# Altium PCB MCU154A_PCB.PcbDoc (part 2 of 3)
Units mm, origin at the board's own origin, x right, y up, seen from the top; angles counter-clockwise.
Board outline 105 x 85 mm, 2 copper layers (Top Layer, Bottom Layer), stack 1.6 mm thick; 186 components, 100 nets, 433 pads, 196 vias.
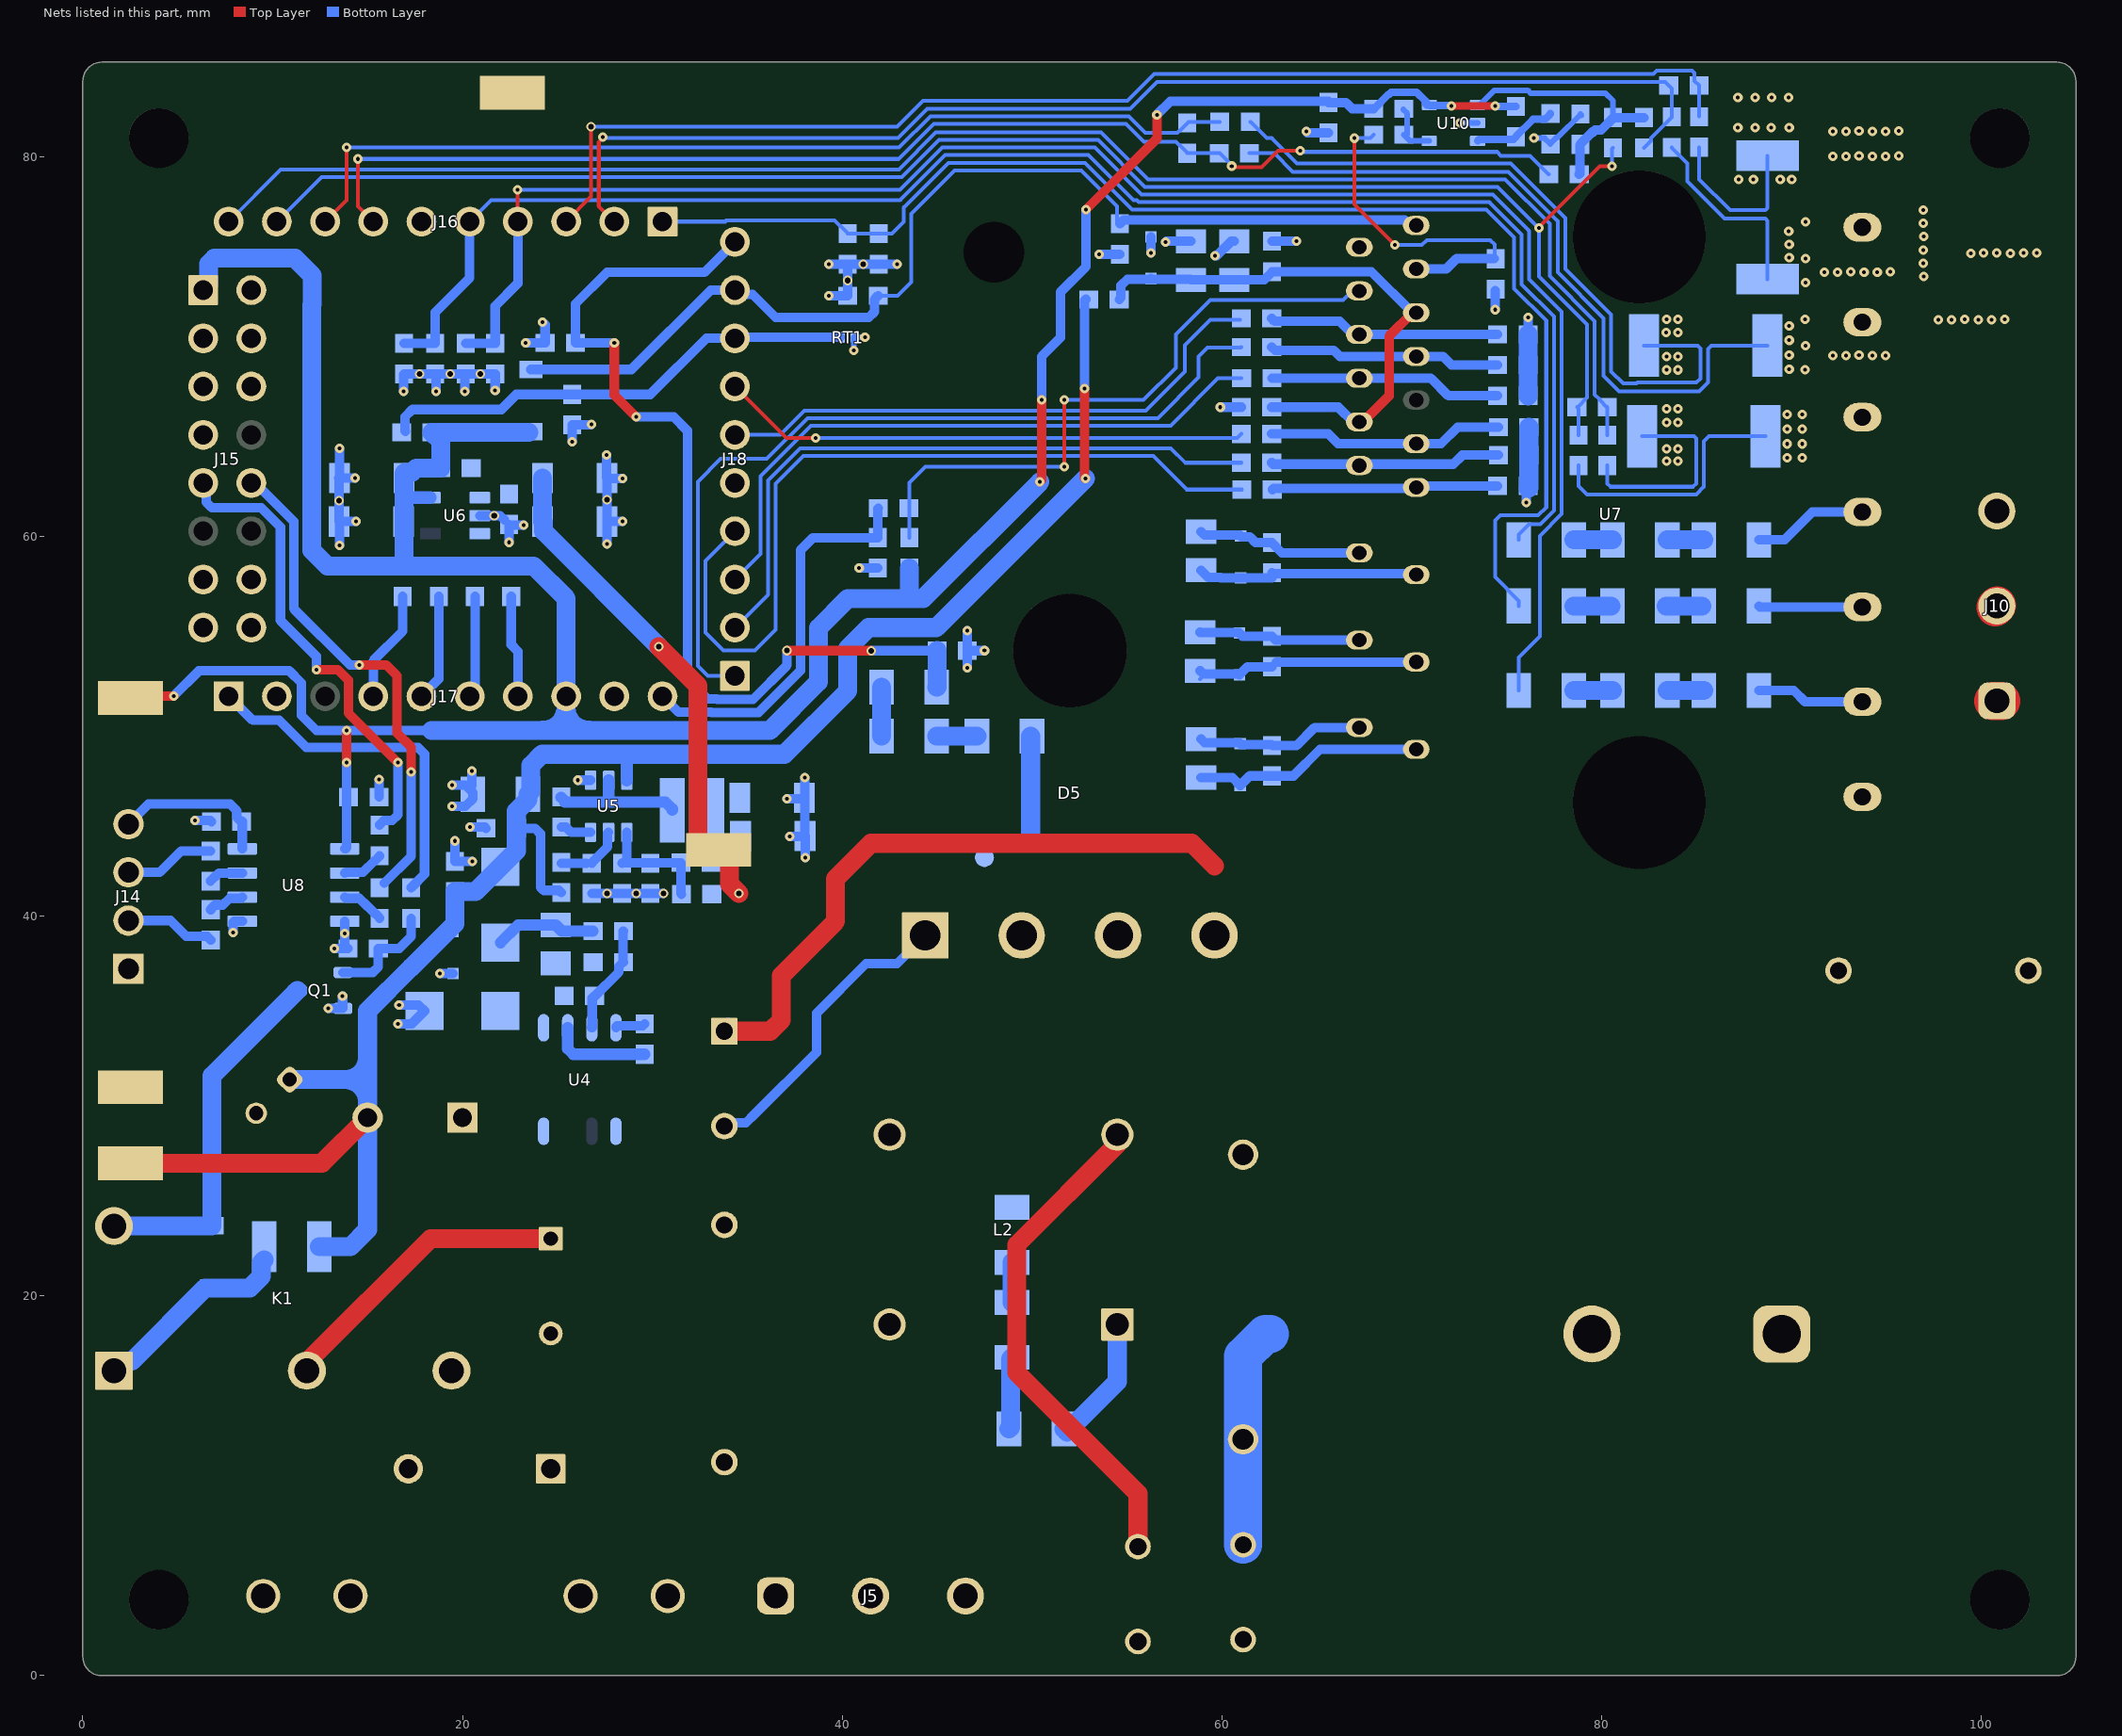
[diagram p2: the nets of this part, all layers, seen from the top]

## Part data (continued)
L3: library part CMP-0064862-2, "Inductor, Shielded Drum Core, Metal Composite, 1.8 mH, 0.35 A, 2.7 ohm, TH", Manufacturer="Wurth Elektronik", Supplier Part Number 1=732-3264-ND, Value1="2.7 ohm", Value2=0.35A, ValueDisplayed=1.8mH
L4: library part CMP-0064362-1, "Inductor, Shielded, Powdered Iron, 6.8 uH, 1.1 A, 0.287 ohm, AEC-Q200 Grade 1, SMD", Manufacturer="Wurth Elektronik", Supplier Part Number 1=732-6942-1-ND, Value1="0.287 ohm", Value2=1.1A, ValueDisplayed=6.8uH
LBL1: library part CMP-0003625-1, "Thermal Transfer Printable Labels, 0.650\" W x 0.200\" H - 10,000 per roll", Manufacturer=Brady, Supplier Part Number 1=97C5133
Logo1: library part CMP-0074844-1
Logo2: library part CMP-0074838-1, "Texas Instrument Corporate Signature"
Logo3: library part CMP-0074847-1, "FCC_disclaimer"
Logo4: library part CMP-0074769-1
LOGO5 LOGO7: library part CMP-0074837-1, "IEC 61010-1 Hot Surface Warning"
LOGO6 LOGO8: library part CMP-0074835-1, "IEC 61010-1 High Voltage Warning"
MP1 MP2 MP3 MP4: library part CMP-0087151-1, Manufacturer="Wurth Electronics"
Q1: library part CMP-0000775-2, "MOSFET, N-CH, 60 V, 0.36 A, SOT-23", Alternate Manufacturer=None, Manufacturer=Nexperia, Supplier Part Number 1=568-5818-1-ND, Value2="0.6 nC"
R8 R55 R85 R88 R97 R98: library part CMP-0022908-4, "RES, 20.0, 1%, 0.1 W, 0603", Manufacturer=Yageo, Power_W=100mW, Supplier Part Number 1=311-20.0HRCT-ND, TempCo="100 ppm/C", Tolerance_%=1%, Value2=0.1W, Value_Code=20R0, ValueDisplayed=20.0
R36 R77 R93 R94 R108: library part CMP-0022895-5, "RES, 1.00 k, 1%, 0.1 W, 0603", Manufacturer=Yageo, Power_W=100mW, Supplier Part Number 1=311-1.00KHRCT-ND, TempCo="100 ppm/C", Tolerance_%=1%, Value2=0.1W, Value_Code=1k00, ValueDisplayed=1.00k
R37: library part CMP-0082820-1, "RES, 180, 1%, 0.5 W, 1210", Manufacturer=Yageo, Power_W=500mW, TempCo="100 ppm/C", Tolerance_%=1%, Value2=0.5W, Value_Code=180R, ValueDisplayed=180
R38 R43 R78 R100 R101 R102 R103: library part CMP-0022746-5, "RES, 10.0 k, 1%, 0.1 W, 0603", Manufacturer=Yageo, Power_W=100mW, Supplier Part Number 1=311-10.0KHRCT-ND, TempCo="100 ppm/C", Tolerance_%=1%, Value2=0.1W, Value_Code=10k0, ValueDisplayed=10.0k
R39: library part CMP-0096764-1, "PTC Thermistor 70 Ohms Disc, 13mm Dia x 7.5mm W", Digikey Part Number=495-76143-ND, Manufacturer=TDK, Mouser Part Number=871-B59770C120A70, Operating Temperature Range="-40°C to +125°C", Tolerance_%=25%
R40 R52: library part CMP-0022786-4, "RES, 133 k, 1%, 0.1 W, 0603", Manufacturer=Yageo, Power_W=100mW, Supplier Part Number 1=311-133KHRCT-ND, TempCo="100 ppm/C", Tolerance_%=1%, Value2=0.1W, Value_Code=133k
R41 R44 R45: library part CMP-0017836-1, "RES, 100 k, 1%, 0.25 W, 1206", Manufacturer="Yageo America", Power_W=250mW, Supplier Part Number 1=311-100KFRCT-ND, TempCo="100 ppm/C", Tolerance_%=1%, Value2=0.25W, Value_Code=100k
R42: library part CMP-0097027-1, "3 kA Varistor 1 Circuit Through Hole Disc 13.2mm", Clamping Voltage=730V, Digikey Part Number=118-ISOM3-275-B-L2-ND, Manufacturer=Bourns, Mouser Part Number=652-ISOM3-275-B-L2, Operating Temperature Range="-40°C to +125°C", ValueDisplayed=30pF
R46 R56 R107 R109: library part CMP-0022906-5, "RES, 20.0 k, 1%, 0.1 W, 0603", Manufacturer=Yageo, Power_W=100mW, Supplier Part Number 1=311-20.0KHRCT-ND, TempCo="100 ppm/C", Tolerance_%=1%, Value2=0.1W, Value_Code=20k0, ValueDisplayed=20.0k
R47 R48 R54 R62 R63 R64 R67 R68 R69 R70 R71 R72: library part CMP-0018207-2, "RES, 332 k, 1%, 0.25 W, 1206", Manufacturer="Yageo America", Power_W=250mW, Supplier Part Number 1=311-332KFRCT-ND, TempCo="100 ppm/C", Tolerance_%=1%, Value2=0.25W, Value_Code=332k
R49: library part CMP-0022898-4, "RES, 1.50 M, 1%, 0.1 W, 0603", Manufacturer=Yageo, Power_W=100mW, Supplier Part Number 1=311-1.50MHRCT-ND, TempCo="100 ppm/C", Tolerance_%=1%, Value2=0.1W, Value_Code=1M50, ValueDisplayed=1.50M
R50: library part CMP-0022735-5, "RES, 100 k, 1%, 0.1 W, 0603", Manufacturer=Yageo, Power_W=100mW, Supplier Part Number 1=311-100KHRCT-ND, TempCo="100 ppm/C", Tolerance_%=1%, Value2=0.1W, Value_Code=100k
R51 R73: library part CMP-0025885-5, "RES, 0, 5%, 0.1 W, 0603", Manufacturer=Yageo, Power_W=100mW, Supplier Part Number 1=311-0.0GRCT-ND, TempCo="200 ppm/C", Tolerance_%=5%, Value2=0.1W, Value_Code=0000, ValueDisplayed=0
R53: library part CMP-0022791-5, "RES, 13.7 k, 1%, 0.1 W, 0603", Manufacturer=Yageo, Power_W=100mW, Supplier Part Number 1=311-13.7KHRCT-ND, TempCo="100 ppm/C", Tolerance_%=1%, Value2=0.1W, Value_Code=13k7, ValueDisplayed=13.7k
R57 R74 R75 R76: library part CMP-0023308-5, "RES, 8.20 k, 1%, 0.1 W, 0603", Manufacturer=Yageo, Power_W=100mW, Supplier Part Number 1=311-8.20KHRCT-ND, TempCo="100 ppm/C", Tolerance_%=1%, Value2=0.1W, Value_Code=8k20, ValueDisplayed=8.20k
R58 R59 R60 R61 R65 R66 R79 R92 R95 R106: library part CMP-0022736-4, "RES, 100, 1%, 0.1 W, 0603", Manufacturer=Yageo, Power_W=100mW, Supplier Part Number 1=311-100HRCT-ND, TempCo="100 ppm/C", Tolerance_%=1%, Value2=0.1W, Value_Code=100R, ValueDisplayed=100
R80 R81 R82: library part CMP-0015791-2, "RES, 0.05, 1%, 2 W, 2512", Manufacturer="Stackpole Electronics Inc", Power_W=2W, Supplier Part Number 1=CSRN2512FT50L0-ND, TempCo="200 ppm/C", Tolerance_%=1%, Value_Code=R050, ValueDisplayed=0.05
R83 R87 R104 R105: library part CMP-0023198-5, "RES, 5.10 k, 1%, 0.1 W, 0603", Manufacturer=Yageo, Power_W=100mW, Supplier Part Number 1=311-5.10KHRCT-ND, TempCo="100 ppm/C", Tolerance_%=1%, Value2=0.1W, Value_Code=5k10, ValueDisplayed=5.10k
RT1: library part CMP-0084566-1, "Thermistor, DEC0002A (X1SON-2)", Alternate Manufacturer="Texas Instruments", Alternate PartNumber=TMP6131DECT
TP6 TP7 TP8 TP9 TP11: library part CMP-0055152-2, "Test Point, Miniature, SMT", Manufacturer="Keystone Electronics", Supplier Part Number 1=36-5015TR-ND
TPDCBUS: library part CMP-0003825-1, "1mm Test Point, SMT", Manufacturer=Any
U4: library part CMP-0074092-1, "700-V Lowest Quiescent Current Off-Line Switcher, D0007A (SOIC-7)", Alternate Manufacturer="Texas Instruments", Alternate PartNumber=UCC28881D
U5: library part CMP-0073969-3, "4.5V to 28V Input, 2A Output, EMI Friendly Synchronous Step-Down Converter, DDC0006A (SOT-23-THIN-6)", Alternate Manufacturer="Texas Instruments", Alternate PartNumber=TPS54202DDCT, Operating Temperature Range="-40 to 125 C", Rating=Catalog
U6: library part CMP-0090171-1, "300-mA low-dropout (LDO) regulator with foldback current limit 5-SOT-23 -40 to 125", Digikey Part Number=296-TLV74033PDBVRCT-ND, Dropout Voltage=460mV, Manufacturer="Texas Instruments", Max Supply Voltage=5.5V, Mouser Part Number=595-TLV74033PDBVR, Nominal Supply Current=50uA, Operating Temperature Range="-40°C to +125°C", Output Voltage=3.3V
U7: library part CMP-0033830-3, "RC-IGBT inverter bridge for three phase DC-to-AC power conversion", Manufacturer="Mitsubishi Electric", Mouser Part Number=917-SLIMDIP-M, Operating Temperature Range="-30°C to +115°C"
U8: library part CMP-0089949-1, "Low Speed, General Purpose, Robust EMC, Dual-Channel Digital Isolators", Manufacturer="Texas Instruments", Max Supply Voltage=5.5V, Min Supply Voltage=1.71V, Operating Temperature Range="to +150°C"
U10: library part CMP-0075716-1, "GENERAL-PURPOSE LOW-VOLTAGE COMPARATOR, DBV0005A (SOT-23-5)", Alternate Manufacturer="Texas Instruments"
XF1 XF2: library part CMP-0003676-1, "Fuse Holder, 10A, TH", Manufacturer=Littelfuse, Supplier Part Number 1=F3784-ND

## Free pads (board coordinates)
  round 0 hole 3.2 unplated: 2(48,75)

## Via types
v1: diameter 0.5, hole 0.2, Top Layer to Bottom Layer, tented both sides, 180 vias
v2: diameter 0.5, hole 0.3, Top Layer to Bottom Layer, tented both sides, 16 vias

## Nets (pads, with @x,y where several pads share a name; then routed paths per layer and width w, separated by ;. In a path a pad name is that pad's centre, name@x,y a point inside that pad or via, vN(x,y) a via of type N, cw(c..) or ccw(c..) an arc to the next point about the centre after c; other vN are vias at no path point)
3.3V: C46.1 C47.1 C81.2 C84.1 D12.1 J15.1 J17.8 R51.2 R77.2 R78.1 R100.1 R101.1 R102.1 R103.1 R107.2 R109.1 TP8.1 U6.5 U8.1 U10.5 | length 170.3
  Top Layer w0.4: v1(72.11,82.69) v1(74.398,82.69)
  Top Layer w0.5: TP8.1@2.5,51.5 2.6,51.6 v1(4.781,51.6) ; v1(13.897,49.791) 13.897,48.103 v1(13.9,48.1) ; v1(50.421,62.89) 50.517,62.985 v1(50.517,67.2) ; v1(52.843,77.236) 56.601,80.993 56.601,82.209 v1(56.583,82.228)
  Bottom Layer w0.4: R109.1@68,82.542 68.025,82.542 68.804,83.322 68.838,83.322 68.934,83.417 70.265,83.417 70.729,82.954 70.729,82.823 70.804,82.748 U10.5@70.929,82.748 70.968,82.709 72.091,82.709 v1(72.11,82.69) ; v1(74.398,82.69) 74.411,82.677 75.493,82.677 R107.2@75.505,82.664
  Bottom Layer w0.5: v1(4.781,51.6) 6.116,52.935 10.878,52.935 11.51,52.303 11.51,50.59 12.309,49.791 v1@13.9,49.791 ; U8.1@13.8,43.555 13.85,43.555 13.9,43.605 v1(13.9,48.1) ; v1@13.9,49.8 18.259,49.8 ; v1(50.517,67.2) 50.517,69.5 51.5,70.483 51.5,72.878 52.843,74.221 v1(52.843,77.236) ; v1(56.583,82.228) 57.286,82.931 C84.1@65.619,82.931 ; C84.1@65.63,82.87 66.552,82.87 66.879,82.542 R109.1@68,82.542
  Bottom Layer w0.65: 16.924,62.06 U6.5@18.309,62.06
  Bottom Layer w1: J15.1@6.34,72.99 6.625,73.275 6.625,74.369 6.926,74.67 11.175,74.67 12.09,73.755 12.09,72.249 12.057,72.216 12.057,59.286 12.89,58.454 R100.1@16.844,58.454 ; 18.374,49.785 25.46,49.785 ; D12.1@23.5,65.5 R77.2@18.4,65.5 18.4,65.485 18.859,65.026 R51.2@18.859,63.612 17.559,63.612 17.336,63.389 16.974,63.389 16.924,63.339 C47.1@16.924,63.089 16.924,62.061 16.924,58.533 R100.1@16.844,58.454 ; 24.221,49.814 ccw(c24.268,50.996) 25.45,50.95 ccw(c26.632,50.996) 26.679,49.814 ; R78.1@43.545,58.35 43.545,56.787 43.5,56.742 ; v1(50.421,62.89) 44.274,56.742 43.5,56.742 ; R100.1@16.844,58.454 R101.1@18.751,58.454 R102.1@20.659,58.454 R103.1@22.566,58.454 23.749,58.454 25.46,56.742 J17.8@25.46,51.6 25.46,49.785 ; 25.46,49.785 36.185,49.785 38.755,52.355 38.755,55.198 40.3,56.742 43.5,56.742
5V: C48.1 C49.1 C50.1 C51.1 C52.1 C53.1 L4.2 R50.2 R51.1 TP7.1 U6.1 U6.3 | length 26.7
  Top Layer w1: v2(30.351,54.206) 32.4,52.156 32.4,43.889 32.789,43.5 TP7.1@33.5,43.5 33.683,43.5 34.072,43.111 34.072,41.697 v2(34.569,41.2)
  Bottom Layer w1: C51.1@24.221,63.089 C52.1@24.221,60.8 24.271,60.75 24.271,60.286 v2(30.351,54.206)
5V_ISO: C82.1 J14.4 U8.8 | length 8.5
  Bottom Layer w0.5: J14.4@2.4,44.86 3.459,45.919 7.756,45.919 8.117,45.557 8.117,45.219 8.342,44.994 8.4,44.994 U8.8@8.4,43.555
15V: C41.1 C44.1 C45.1 D4.2 D6.1 L3.2 R37.1 R46.2 R49.2 R73.1 TP6.1 U5.3 | length 106
  Top Layer w0.5: v1(52.774,67.811) 52.774,63.102 v1(52.816,63.06)
  Top Layer w1: TP6.1@2.5,27 12.6,27 L3.2@15,29.4
  Bottom Layer w0.5: C45.1@22.838,44.641 23.817,44.641 24.11,44.348 24.11,41.545 24.284,41.371 25.081,41.371 R49.2@25.2,41.252 ; v1(52.774,67.811) 52.774,72.442 R73.1@52.837,72.506
  Bottom Layer w0.65: U5.3@28.65,47.175 28.65,48.542
  Bottom Layer w1: C41.1@10.9,31.4 14.792,31.4 15,31.608 ; R37.1@12.45,22.6 14.1,22.6 15,23.5 L3.2@15,29.4 15,31.608 ; L3.2@15,30.171 ccw(c13.818,30.218) 13.864,31.4 ccw(c13.818,32.582) 15,32.629 ; v1(52.816,63.06) 44.966,55.21 41.395,55.21 40.3,54.116 40.3,51.877 36.965,48.542 28.65,48.542 24.186,48.542 23.6,47.957 23.6,46.576 C44.1@23.45,46.426 23.45,46.151 22.838,45.539 C45.1@22.838,44.641 22.838,43.452 D4.2@22,42.614 20.686,41.3 R46.2@19.6,41.3 19.6,39.606 17.305,37.311 17.295,37.311 15,35.016 15,31.608
EGND: C33.2 C40.1 J5.3
GND: C32.2 C38.2 C41.2 C42.1 C44.2 C45.2 C46.2 C47.2 C49.2 C50.2 C51.2 C52.2 C53.2 C56.2 C59.2 C64.1 C65.1 C66.1 C67.1 C68.1 C69.1 C70.2 C71.2 C72.2 C73.2 C74.2 C75.2 C76.2 C77.2 C78.1 C79.2 C81.1 C83.2 C84.2 D5.4 D6.2 D7.2 D11.2 J15.2 J15.7 J16.6 J17.9 J18.5 Q1.2 R38.1 R46.1 R52.1 R53.1 R56.1 R57.1 R74.1 R75.1 R76.1 R80.1 R81.1 R82.1 R83.1 R88.1 R97.1 R98.1 R108.1 RT1.1 TP9.1 TP11.1 U5.1 U6.2 U7.19 U8.4 U10.2 | length 178
  Top Layer w1: TP11.1@22.419,83.59 TP11.1@22.626,83.382 ; C42.1@33.8,33.95 36.214,33.95 36.8,34.536 36.8,36.883 39.655,39.738 39.655,41.986 41.519,43.85 58.431,43.85 59.62,42.661
  Top Layer w2: D5.4@59.534,39.086 D5.4@59.62,39
  Bottom Layer w0.2: R88.1@61.502,81.859 61.527,81.859 62.386,81 62.635,81 63.964,79.67 75.22,79.67 78.1,76.79 78.1,74.115 80.518,71.697 80.518,68.708 81.158,68.068 81.841,68.068 81.891,68.118 85.003,68.118 85.216,68.331 85.216,69.924 85.072,70.068 R81.1@82.25,70.068 ; R97.1@80.315,63.75 80.315,62.797 80.48,62.633 84.825,62.633 84.997,62.805 84.997,65.18 84.88,65.297 R82.1@82.147,65.297 ; R98.1@85.152,80.518 85.152,78.832 86.782,77.203 88.637,77.203 88.754,77.32 R80.1@88.754,80.073
  Bottom Layer w0.3: v1(40.625,69.809) RT1.1@40.625,70.5 v1(41.2,70.5) ; v1(72.554,81.798) U10.2@73.479,81.798 ; C83.2@74.35,73.044 C83.2@74.4,72.994 ; v1(76.453,81) 77.006,81 R108.1@77.32,80.687 77.32,80.712 77.645,81.037 77.693,81.037 78.897,82.241 C79.2@78.897,82.266 C79.2@78.958,82.204
  Bottom Layer w0.5: v1(12.921,35.15) Q1.2@13.7,35.15 13.683,35.167 v1(13.683,35.81) ; v1(13.244,38.308) R38.1@13.968,38.309 13.8,38.477 v1(13.8,39.1) U8.4@13.8,39.745 ; C47.2@13.474,63.089 v1(14.34,63.089) ; v1(13.517,59.549) C46.2@13.517,60.783 ; v1(13.517,64.65) 13.517,63.095 C47.2@13.524,63.089 13.5,63.065 v2(13.5,61.9) C46.2@13.5,60.8 C46.2@13.517,60.783 ; v1(14.4,60.8) 13.534,60.8 C46.2@13.517,60.783 ; C81.1@15.6,46.285 v1(15.6,47.219) ; v1(16.6,34.337) 16.61,34.346 17.33,34.346 D7.2@18,35.016 17.682,35.334 v1(16.662,35.334) ; v1(16.9,67.648) 16.9,68.555 R76.1@16.923,68.578 C71.2@18.559,68.578 ; v1(18.61,67.648) 18.61,68.528 C71.2@18.559,68.578 ; v1(18.8,37) D6.2@19.5,37 ; v1(19.461,45.8) 20.15,45.8 20.55,46.2 20.55,46.513 20.15,46.913 v1(19.461,46.913) ; v1(19.6,43.975) R46.1@19.6,42.9 v1(20.514,42.9) ; v1(20.112,67.648) 20.112,68.525 R74.1@20.166,68.578 ; v1(20.4,44.7) 21.179,44.7 C45.2@21.238,44.641 ; C44.2@20.5,46.884 v1(20.5,47.663) ; U6.2@20.909,61.11 v2(21.674,61.11) 21.987,61.11 C53.2@22.202,60.895 ; v1(21.721,67.702) C73.2@21.721,68.578 R74.1@20.166,68.578 ; v1(22.452,59.705) C53.2@22.452,60.645 22.497,60.6 v1(23.221,60.6) ; v1(23.334,70.209) C56.2@24.352,70.209 24.352,71.169 v1(24.221,71.3) ; v1(25.781,65) C76.2@25.781,65.895 v1@26.781,65.895 ; v1(26.081,47.175) U5.1@26.75,47.175 ; R52.1@26.811,41.2 R53.1@28.401,41.2 v2(29.146,41.2) R56.1@29.891,41.2 29.905,41.214 v2(30.587,41.214) ; v1(27.6,64.3) 27.6,63.109 C51.2@27.621,63.089 ; v1(27.606,59.627) 27.606,60.785 C52.2@27.621,60.8 ; v1(28.432,60.8) C52.2@27.621,60.8 ; v1(28.432,63.06) 27.649,63.06 C51.2@27.621,63.089 ; v1(37.1,46.2) 37.959,46.2 C50.2@38.009,46.25 ; v1(37.239,44.212) 38.03,44.212 C49.2@38.049,44.23 ; v1(38.029,47.31) 38.029,46.27 C50.2@38.009,46.25 ; v1(38.067,43.1) 38.067,44.212 C49.2@38.049,44.23 ; v1(39.3,72.7) C78.1@40.3,72.7 R75.1@40.3,74.363 ; v1(39.3,74.363) R75.1@40.3,74.363 ; v1(40.9,58.35) C77.2@41.883,58.35 ; v1(42.9,74.363) C70.2@41.933,74.363 R75.1@40.3,74.363 ; v1(46.6,53.1) R57.1@46.6,54 ; v1(46.6,55.052) R57.1@46.6,54 ; v1(47.5,54) R57.1@46.6,54 ; v1(53.543,74.882) R83.1@54.625,74.882 ; D11.2@56.274,75.799 56.274,74.963 v1(56.279,74.958) ; v1(57.049,75.512) 57.101,75.564 C72.2@58.386,75.564 ; v1(59.646,74.799) 59.733,74.799 60.497,75.564 C32.2@60.662,75.564 ; v1(59.929,66.825) C74.2@61.035,66.825 ; C75.2@62.646,75.564 v1(63.945,75.564) ; v1(64.459,81.342) 64.52,81.28 C84.2@65.619,81.28 ; v1(74.4,71.96) C83.2@74.4,72.965 ; v1(76.053,61.791) 76.053,62.454 C64.1@76.14,62.541 ; C69.1@76.14,71.049 v1(76.14,71.558) ; C71.2@18.559,68.578 R74.1@20.166,68.578 ; C52.2@27.621,60.8 C51.2@27.621,63.089 ; C50.2@38.009,46.25 38.029,46.23 38.029,44.25 C49.2@38.049,44.23
  Bottom Layer w1: C42.1@33.8,33.95 C42.1@34,34.15 ; C64.1@76.14,62.541 76.178,62.579 C66.1@76.178,64.297 ; C65.1@76.14,67.424 C67.1@76.14,69.04 C69.1@76.14,70.65 ; C66.1@76.178,64.322 C68.1@76.178,65.772
  other v1: 83.437,63.99 84.036,63.99 83.437,64.635 84.036,64.635 26.8,65.914 83.437,66.018 84.036,66.018 83.437,66.731 84.036,66.731 83.437,68.787 84.036,68.787 83.437,69.5 84.036,69.483 84.036,70.749 83.418,70.757 83.437,71.462 84.036,71.462 87.237,78.823 88.015,78.823 89.429,78.823 90.027,78.823 87.196,81.554 88.107,81.554 88.953,81.554 89.9,81.554 87.196,83.13 88.107,83.13 88.966,83.13 89.865,83.13
  other v2: 27.606,41.2 27.621,61.944 17.741,68.578 19.362,68.578 20.944,68.578 40.3,73.5 41.116,74.363
GND_ISO: C82.2 J14.1 U8.5 | length 1.9
  Bottom Layer w0.5: v1(5.9,45.05) 6.711,45.05 C82.2@6.767,44.994 ; v1(7.924,39.15) 7.924,39.695 7.974,39.745 U8.5@8.4,39.745
IPM_15V: C32.1 C72.1 C74.1 C75.1 D11.1 R73.2 U7.11 U7.16 | length 29.7
  Top Layer w0.5: U7.11@67.25,66.05 67.45,66.05 68.816,67.416 68.816,70.566 70.05,71.8 U7.16@70.25,71.8
  Bottom Layer w0.5: R73.2@54.6,72.5 54.687,72.587 54.687,73.225 55.028,73.566 D11.1@56.274,73.566 ; D11.1@56.274,73.599 56.308,73.566 58.352,73.566 C72.1@58.386,73.532 C32.1@60.662,73.532 62.239,73.532 62.646,73.939 C75.1@62.646,73.964 67.886,73.964 70.05,71.8 U7.16@70.25,71.8 ; C74.1@62.635,66.825 66.14,66.825 66.915,66.05 U7.11@67.25,66.05
IPM_CIN: C83.1 R106.2 U7.18 | length 18.3
  Top Layer w0.2: v1(66.991,80.993) 66.991,77.507 v1(69.131,75.367)
  Bottom Layer w0.2: v1(66.991,80.993) 66.922,80.993 66.915,81 67.827,81 R106.2@68,81.173 ; v1(69.131,75.367) 70.549,75.367 70.809,75.627 74.147,75.627 74.38,75.394 74.38,74.674 C83.1@74.35,74.644
  Bottom Layer w0.5: U7.18@70.25,74.1 71.821,74.1 72.365,74.644 C83.1@74.35,74.644
IPM_FAULT: C77.1 J17.10 R79.1 | length 20.8
  Bottom Layer w0.5: J17.10@30.54,51.6 31.387,50.753 33.108,50.753 33.126,50.735 35.594,50.735 37.805,52.947 37.805,59.287 38.468,59.95 C77.1@41.883,59.95 41.883,61.465 R79.1@41.914,61.496
IPM_PWM_UH: C64.2 R58.2 U7.8 | length 12
  Bottom Layer w0.5: R58.2@62.662,62.484 62.721,62.542 70.192,62.542 70.329,62.679 C64.2@74.54,62.679
IPM_PWM_UL: C65.2 R59.2 U7.13 | length 12.3
  Bottom Layer w0.5: R59.2@62.644,68.349 U7.13@67.25,68.35 71.017,68.35 71.942,67.424 C65.2@74.54,67.424
IPM_PWM_VH: C66.2 R60.2 U7.9 | length 12.2
  Bottom Layer w0.5: R60.2@62.635,63.898 62.709,63.824 67.176,63.824 U7.9@67.25,63.75 ; U7.9@67.25,63.824 72.204,63.824 72.678,64.297 C66.2@74.578,64.297
IPM_PWM_VL: C67.2 R61.2 U7.14 | length 12.3
  Bottom Layer w0.5: R61.2@62.635,69.992 62.818,69.809 65.908,69.809 66.217,69.5 U7.14@70.25,69.5 71.65,69.5 72.11,69.04 C67.2@74.54,69.04
IPM_PWM_WH: C68.2 R65.2 U7.10 | length 12.5
  Bottom Layer w0.5: R65.2@62.635,65.414 65.619,65.414 66.133,64.9 U7.10@70.25,64.9 71.56,64.9 72.432,65.772 C68.2@74.578,65.772
IPM_PWM_WL: C69.2 R66.2 U7.15 | length 12.3
  Bottom Layer w0.5: R66.2@62.635,71.502 62.79,71.347 66.217,71.347 66.915,70.65 U7.15@67.25,70.65 C69.2@74.54,70.65
IPM_TEMP_AD: C78.2 D12.2 J18.9 R83.2 U7.20 | length 56.5
  Bottom Layer w0.2: C78.2@41.9,72.7 42.935,72.7 43.644,73.409 43.644,77.018 45.926,79.3 52.6,79.3 54.491,77.409 54.491,76.616 R83.2@54.625,76.482
  Bottom Layer w0.5: D12.2@23.61,68.808 28.898,68.808 33.08,72.99 J18.9@34.36,72.99 34.58,72.77 35.279,72.77 36.5,71.549 41.407,71.549 41.7,71.842 41.7,72.5 C78.2@41.9,72.7 ; R83.2@54.625,76.482 54.822,76.679 69.636,76.679 69.915,76.4 U7.20@70.25,76.4
IU_N: C54.1 J16.10 R97.2 | length 85.9
  Bottom Layer w0.2: J16.10@7.68,76.6 10.43,79.35 42.987,79.35 44.937,81.3 53.648,81.3 56.119,78.829 74.93,78.829 77.275,76.484 77.275,73.727 79.654,71.348 79.654,67.486 79.915,67.225 79.915,67.2 80.29,66.825 C54.1@80.315,66.825 R97.2@80.315,65.35
IU_P: C54.2 J16.9 R85.2 R87.1 | length 88.6
  Top Layer w0.2: v1(76.725,76.256) 76.725,76.315 79.919,79.509 v1(80.566,79.509)
  Bottom Layer w0.2: J16.9@10.22,76.6 12.57,78.95 43.153,78.95 45.103,80.9 53.481,80.9 55.952,78.429 74.522,78.429 76.694,76.256 v1(76.725,76.256) ; v1@76.71,76.241 76.725,76.226 76.725,73.712 79.254,71.182 79.254,67.339 78.74,66.825 C54.2@78.715,66.825 78.807,66.732 R85.2@78.807,65.35 ; v1(80.566,79.509) 80.566,80.429 R87.1@80.618,80.48
IV_N: C31.1 J16.8 R88.2 | length 51.7
  Top Layer w0.2: J16.8@12.76,76.6 13.9,77.74 v1(13.9,80.5)
  Bottom Layer w0.2: v1(13.9,80.5) 43.006,80.5 44.66,82.154 55.111,82.154 55.978,81.286 57.669,81.286 57.783,81.4 57.808,81.4 58.267,81.859 R88.2@59.902,81.859
IV_P: C31.2 J16.7 R55.2 R104.1 | length 69
  Top Layer w0.2: v1(14.5,79.9) 14.5,77.4 J16.7@15.3,76.6 ; v1(60.526,79.526) 60.579,79.474 62.106,79.474 62.958,80.326 v1(64.134,80.326)
  Bottom Layer w0.2: v1(14.5,79.9) 42.972,79.9 44.825,81.754 54.945,81.754 55.893,80.806 57.577,80.806 57.783,80.6 57.808,80.6 58.183,80.225 C31.2@58.183,80.2 R55.2@59.862,80.2 59.887,80.2 60.526,79.56 v1(60.526,79.526) ; v1(64.134,80.326) 64.188,80.273 74.511,80.273 74.713,80.07 76.236,80.07 77.208,79.098 R104.1@77.233,79.098
IW_N: C19.1 J16.3 R98.2 | length 67.3
  Top Layer w0.2: J16.3@25.46,76.6 26.781,77.921 v2(26.781,81.6)
  Bottom Layer w0.2: v2(26.781,81.6) 42.9,81.6 44.254,82.954 55.02,82.954 56.438,84.372 82.752,84.372 82.928,84.548 84.78,84.548 84.91,84.417 84.91,84.015 C19.1@85.152,83.773 R98.2@85.152,82.143
IW_P: C19.2 J16.2 R8.2 R105.1 | length 66.3
  Top Layer w0.2: v1(27.4,81.05) 27.4,81.002 27.181,80.783 27.181,77.419 J16.2@28,76.6
  Bottom Layer w0.2: v1(27.4,81.05) 27.45,81 42.94,81 44.494,82.554 55.186,82.554 56.596,83.964 83.361,83.964 83.715,83.61 R8.2@83.715,82.115 83.715,82.09 82.625,81 82.625,80.855 R105.1@82.25,80.48
LINE: J5.1 XF1.1 XF1.2
MCU_TCK: J15.4
MCU_TDI: J15.5
MCU_TDO: J15.6
MCU_TMS: J15.3
MISC_IO: J17.2
MOTOR_TEMP_AD: C76.1 J18.8 R77.1 RT1.2 | length 25.4
  Bottom Layer w0.5: R77.1@17.005,65.538 16.974,65.57 16.974,66.313 17.361,66.7 22.045,66.7 22.84,67.495 C76.1@25.781,67.495 29.891,67.495 32.846,70.45 J18.8@34.36,70.45 34.41,70.5 RT1.2@39.9,70.5
MOTOR_U: J10.1 R62.2 U7.26 | length 6.1
  Top Layer w2: J10.1@100.645,51.351 J10.1@101.065,51.351
  Bottom Layer w0.5: R62.2@88.297,51.9 90.141,51.9 90.741,51.3 U7.26@93.75,51.3
MOTOR_V: J10.2 R63.2 U7.25 | length 5.6
  Top Layer w2: J10.2@100.752,56.287 J10.2@100.852,56.387
  Bottom Layer w0.5: R63.2@88.297,56.351 88.348,56.3 U7.25@93.75,56.3
MOTOR_W: J10.3 R64.2 U7.24 | length 6.1
  Bottom Layer w0.5: R64.2@88.297,59.835 89.654,59.835 91.118,61.3 U7.24@93.75,61.3
NetC33_1: C33.1 C39.1 D5.2 L2.2 R41.2 | length 26
  Top Layer w1: L2.2@54.5,28 49.2,22.7 49.2,15.973 55.588,9.585 C33.1@55.588,6.8
NetC34_1: C34.1 K1.3 L2.3 R39.2
NetC35_1: C35.1 R40.1 R43.2 U4.3 | length 5.8
  Bottom Layer w0.5: U4.3@26.796,34.15 U4.3@26.815,34.131 26.834,34.15 26.834,35.687 C35.1@26.956,35.81 26.981,35.81 28.23,37.058 28.23,37.358 28.455,37.583 R43.2@28.457,37.583 ; R43.2@28.48,37.583 28.469,37.595 28.469,39.211 R40.1@28.48,39.222
NetC35_2: C35.2 C36.2 C37.2 D7.1 L3.1 R43.1 U4.1 U4.2 | length 5.3
  Bottom Layer w0.6: U4.2@25.545,34.131 25.545,33.029 25.838,32.737 C36.2@29.6,32.737
NetC36_1: C36.1 U4.4 | length 1.6
  Bottom Layer w0.5: U4.4@28.085,34.131 28.085,34.188 28.131,34.234 29.497,34.234 C36.1@29.6,34.337
NetC37_1: C37.1 D4.1 R40.2 | length 5.4
  Bottom Layer w0.6: D4.1@22,38.614 22.933,39.547 C37.1@24.907,39.547 25.232,39.222 R40.2@26.88,39.222
NetC39_2: C39.2 C40.2 D5.3 L2.1 R45.1 | length 18.8
  Bottom Layer w1: R45.1@51.689,13 51.851,12.838 54.5,15.487 L2.1@54.5,18.5
  Bottom Layer w2: C40.2@61.126,6.9 C39.2@61.126,12.45 61.126,16.828 62.297,18 62.55,18
NetC43_1: C43.1 U5.6 | length 1.7
  Bottom Layer w0.5: C43.1@25.2,44.7 25.46,44.7 25.735,44.425 U5.6@26.75,44.425
NetC43_2: C43.2 L4.1 U5.2 | length 7.4
  Bottom Layer w0.6: C43.2@25.198,46.275 25.373,46.1 25.373,46.015 25.375,46.013 27.7,46.013 ; U5.2@27.7,47.175 27.7,46.013 ; L4.1@31.05,45.595 31.05,45.663 30.7,46.013 27.7,46.013
NetC48_2: C48.2 R50.1 R53.2 R56.2 U5.4 | length 6.1
  Bottom Layer w0.5: R53.2@28.401,42.8 28.432,42.831 C48.2@31.507,42.831 31.507,41.199 R50.1@31.537,41.169 ; R53.2@28.65,43.074 U5.4@28.65,44.425
NetC57_1: C57.1 C58.1 D8.2 U7.2 | length 12.3
  Bottom Layer w0.5: C57.1@58.913,47.31 60.564,47.31 D8.2@60.974,46.9 61.474,47.4 C58.1@62.644,47.4 63.781,47.4 65.181,48.8 U7.2@70.25,48.8
NetC57_2: C57.2 C58.2 D8.1 U7.3 | length 8.9
  Bottom Layer w0.5: C57.2@58.913,49.342 59.105,49.15 60.924,49.15 D8.1@60.974,49.1 61.024,49.05 62.619,49.05 62.669,49 63.945,49 64.895,49.95 U7.3@67.25,49.95
NetC60_1: C60.1 C61.1 D9.2 U7.4 | length 11.5
  Bottom Layer w0.2: C60.1@58.864,52.502 C60.1@58.903,52.541
  Bottom Layer w0.5: C60.1@58.864,52.936 59.027,52.773 60.876,52.773 D9.2@60.926,52.723 61.355,53.152 C61.1@62.644,53.152 ; C61.1@62.869,53.4 U7.4@70.25,53.4
NetC60_2: C60.2 C61.2 D9.1 U7.5 | length 8.6
  Bottom Layer w0.5: C60.2@58.864,54.968 58.887,54.945 60.903,54.945 D9.1@60.926,54.923 61.097,54.752 C61.2@62.644,54.752 62.845,54.55 U7.5@67.25,54.55
NetC62_1: C62.1 C63.1 D10.2 U7.6 | length 11.5
  Bottom Layer w0.5: C62.1@58.913,58.233 59.298,57.848 59.937,57.848 59.949,57.835 D10.2@60.999,57.835 C63.1@62.646,57.835 ; C63.1@62.646,58.1 62.696,58.05 70.2,58.05 U7.6@70.25,58
NetC62_2: C62.2 C63.2 D10.1 U7.7 | length 8.8
  Bottom Layer w0.5: C62.2@58.913,60.265 59.092,60.085 60.949,60.085 D10.1@60.999,60.035 61.049,59.985 61.488,59.985 61.773,59.7 C63.2@62.646,59.7 62.646,59.675 63.171,59.15 U7.7@67.25,59.15
NetC79_1: C79.1 R87.2 R104.2 R105.2 U10.1 | length 14.1
  Bottom Layer w0.3: U10.1@73.479,82.748 73.604,82.748 74.37,83.514 76.125,83.514 76.267,83.372 80.208,83.372 80.618,82.963 R87.2@80.618,82.08 R87.2@80.618,82.055
  Bottom Layer w0.5: R104.2@78.833,79.098 78.865,79.13 78.865,80.634 C79.1@78.897,80.666 78.897,80.691 79.522,81.316 79.558,81.316 79.672,81.43 79.993,81.43 R87.2@80.618,82.055 ; R87.2@80.618,82.08 R105.2@82.25,82.08
NetD3_1: D3.1 K1.1 R37.2 | length 10.7
  Bottom Layer w1: K1.1@1.64,16.065 2.14,16.565 2.58,16.565 6.44,20.425 8.793,20.425 9.4,21.032 9.4,21.75 R37.2@9.55,21.9
NetD3_2: D3.2 K1.5 Q1.3 | length 19.4
  Bottom Layer w1: K1.5@1.64,23.685 1.655,23.7 D3.2@6.8,23.7 6.8,31.6 Q1.3@11.3,36.1
NetK1_2: K1.2 R39.1 R42.2 XF2.1 XF2.2 | length 15.6
  Top Layer w1: K1.2@11.8,16.5 18.325,23.025 R39.1@24.65,23.025
NetQ1_1: Q1.1 R36.2 R38.2 | length 5.9
  Bottom Layer w0.5: Q1.1@13.7,37.05 15.275,37.05 15.568,37.343 R38.2@15.568,38.309 16.662,38.309 17.3,38.947 R36.2@17.3,39.9
NetR8_1: R8.1 R80.2 U7.21 | length 10.3
  Bottom Layer w0.2: R8.1@83.715,80.515 83.715,80.49 84.533,79.672 84.533,78.725 86.492,76.766 88.637,76.766 88.754,76.649 R80.2@88.754,73.573
  other v1: 90.754,73.39 96.988,73.719 91.746,73.94 92.44,73.94 93.846,73.94 94.54,73.94 93.13,73.964 95.23,73.964 96.964,74.409 90.754,74.644 89.9,74.707 99.456,74.934 101.556,74.934 100.146,74.957 100.84,74.957 102.246,74.957 102.94,74.957 96.964,75.103 89.9,75.401 96.988,75.819 89.876,76.091 96.964,76.509 90.754,76.583 96.964,77.203 92.189,80.03 92.883,80.03 94.289,80.03 94.983,80.03 93.573,80.054 95.673,80.054 92.189,81.343 92.883,81.343 94.289,81.343 94.983,81.343 93.573,81.367 95.673,81.367
NetR41_1: R41.1 R44.2 | length 2.1
  Bottom Layer w1: R44.2@48.952,19.663 R41.1@48.952,21.773
NetR44_1: R44.1 R45.2 | length 3.8
  Bottom Layer w1: R45.2@48.789,13 48.87,13.081 48.87,16.682 R44.1@48.952,16.763
NetR47_1: R47.1 R48.2 | length 2.1
  Bottom Layer w1: R48.2@44.985,49.5 R47.1@47.105,49.5
NetR48_1: R48.1 R54.2 | length 2.6
  Bottom Layer w1: R48.1@42.085,49.5 R54.2@42.085,52.073
NetR49_1: R49.1 R52.2 U5.5 | length 3.3
  Bottom Layer w0.5: R49.1@25.2,42.8 R52.2@26.532,42.8 ; R52.2@26.811,42.8 26.811,42.825 27.65,43.664 27.65,44.375 U5.5@27.7,44.425
NetR55_1: R55.1 R81.2 U7.22 | length 37.9
  Bottom Layer w0.2: R55.1@61.462,80.2 62.77,80.2 63.741,79.229 75.096,79.229 77.7,76.625 77.7,73.925 80.118,71.508 80.118,68.484 80.934,67.668 85.152,67.668 85.616,68.131 85.616,69.881 85.803,70.068 R81.2@88.75,70.068
  other v1: 90.733,68.794 89.9,68.832 92.189,69.538 92.883,69.538 94.289,69.538 94.983,69.538 89.9,69.562 93.573,69.562 90.757,70.068 89.9,70.35 89.9,71.102 90.733,71.452 97.76,71.438 98.454,71.438 99.144,71.462 99.86,71.438 100.554,71.438 101.244,71.462
NetR62_1: R62.1 R67.2 | length 1.9
  Bottom Layer w1: R67.2@83.479,51.9 R62.1@85.397,51.9
NetR63_1: R63.1 R68.2 | length 1.9
  Bottom Layer w1: R68.2@83.418,56.351 R63.1@85.304,56.351
NetR64_1: R64.1 R69.2 | length 1.9
  Bottom Layer w1: R69.2@83.479,59.835 R64.1@85.397,59.835
NetR67_1: R67.1 R70.2 | length 2
  Bottom Layer w1: R70.2@78.55,51.9 R67.1@80.579,51.9
NetR68_1: R68.1 R71.2 | length 2
  Bottom Layer w1: R71.2@78.55,56.351 R68.1@80.518,56.351
NetR69_1: R69.1 R72.2 | length 2
  Bottom Layer w1: R72.2@78.55,59.835 R69.1@80.579,59.835
NetR78_2: R78.2 R79.2 U7.17 | length 33.9
  Top Layer w0.2: v1(51.7,63.69) v1(51.7,67.2)
  Bottom Layer w0.2: R78.2@43.545,59.95 43.545,62.841 44.393,63.69 v1(51.7,63.69) ; v1(51.7,67.2) 55.872,67.2 57.577,68.905 57.577,70.655 59.392,72.47 66.399,72.47 66.879,72.95 U7.17@67.25,72.95
NetR82_2: R82.2 R85.1 U7.23 | length 13.8
  Bottom Layer w0.2: R85.1@78.807,63.75 78.807,62.679 79.254,62.233 79.876,62.233 84.997,62.233 85.397,62.633 85.397,65.024 85.67,65.297 R82.2@88.647,65.297
  other v1: 89.797,64.161 90.59,64.161 89.797,64.891 90.59,64.891 89.797,65.679 90.59,65.679 89.797,66.431 90.59,66.431
NetR92_2: R92.2 U8.2 | length 2.2
  Bottom Layer w0.5: U8.2@13.8,42.285 13.85,42.335 14.768,42.335 15.383,42.95 15.408,42.95 15.633,43.175 R92.2@15.633,43.2
NetR93_1: R93.1 U8.7 | length 1.9
  Bottom Layer w0.5: R93.1@6.734,41.85 6.734,41.875 6.959,42.1 6.984,42.1 7.169,42.285 U8.7@8.4,42.285
NetR94_2: R94.2 U8.3 | length 2.3
  Bottom Layer w0.5: U8.3@13.8,41.015 13.85,40.965 14.556,40.965 14.971,40.55 14.983,40.55 15.383,40.15 15.408,40.15 15.633,39.925 R94.2@15.633,39.9
NetR95_1: R95.1 U8.6 | length 2
  Bottom Layer w0.5: R95.1@6.738,40.35 6.738,40.375 6.963,40.6 7.375,40.6 7.74,40.965 8.35,40.965 U8.6@8.4,41.015
NetR106_1: R106.1 R109.2 U10.4 | length 2.9
  Bottom Layer w0.3: R109.2@69.564,82.506 69.772,82.298 R106.1@69.772,81.173 ; R106.1@69.6,81.173 69.924,80.848 U10.4@70.929,80.848
NetR107_1: R107.1 R108.2 U10.3 | length 4.5
  Bottom Layer w0.4: U10.3@73.479,80.848 73.554,80.923 75.365,80.923 R107.1@75.505,81.064 75.505,81.089 76.404,81.987 77.045,81.987 77.32,82.262 R108.2@77.32,82.287
NEU: C34.2 J5.2 L2.4 R42.1
PWM_UH: J18.4 R58.1 | length 44.1
  Bottom Layer w0.2: J18.4@34.36,60.29 32.8,58.73 32.8,54.943 33.743,54 35.397,54 36.5,55.104 36.5,62.8 37.95,64.25 56.393,64.25 58.159,62.484 R58.1@61.062,62.484
PWM_UL: J18.3 R59.1 | length 33.5
  Bottom Layer w0.2: J18.3@34.36,57.75 35.7,59.09 35.7,63.202 38.348,65.85 57.302,65.85 59.801,68.349 R59.1@61.044,68.349
PWM_VH: J18.2 R60.1 | length 34.4
  Bottom Layer w0.2: J18.2@34.36,55.21 36.1,56.95 36.1,61.995 36.1,62.783 36.1,62.966 37.784,64.65 37.967,64.65 38.755,64.65 57.32,64.65 58.073,63.898 R60.1@61.035,63.898
PWM_VL: J18.1 R61.1 | length 44.1
  Bottom Layer w0.2: J18.1@34.36,52.67 32.93,52.67 32.4,53.2 32.4,62.9 33.6,64.1 36.032,64.1 38.182,66.25 56.64,66.25 58.784,68.393 58.784,69.488 59.257,69.962 61.004,69.962 R61.1@61.035,69.992
PWM_WH: J18.7 R65.1 | length 27.9
  Top Layer w0.2: J18.7@34.36,67.91 37.07,65.2 v1(38.6,65.2)
  Bottom Layer w0.2: v1(38.6,65.2) 60.821,65.2 R65.1@61.035,65.414
PWM_WL: J18.6 R66.1 | length 29.9
  Bottom Layer w0.2: J18.6@34.36,65.37 36.737,65.37 38.017,66.65 55.999,66.65 58.058,68.708 58.058,70.093 59.392,71.427 R66.1@60.96,71.427
RELAY: J17.1 R36.1 | length 18.9
  Bottom Layer w0.5: J17.1@7.68,51.6 8.95,50.33 10.345,50.33 11.775,48.9 17.657,48.9 18,48.557 18,42.225 17.3,41.525 R36.1@17.3,41.5
SPI_CLK(AI): J17.5 R101.2 | length 5.6
  Bottom Layer w0.5: J17.5@17.84,51.6 18.751,52.511 R101.2@18.751,56.854
SPI_CLK(DAC): J15.13
SPI_PICO(AI): J17.4 R100.2 | length 5.9
  Bottom Layer w0.5: J17.4@15.3,51.6 15.3,53.475 16.844,55.019 R100.2@16.844,56.854
SPI_PICO(DAC): J15.14
SPI_POCI(AI): J17.7 R103.2 | length 5.4
  Bottom Layer w0.5: R103.2@22.566,56.854 22.566,54.316 22.92,53.963 J17.7@22.92,51.6
SPI_POCI(DAC): J15.15
SPI_PTE(AI): J17.6 R102.2 | length 5.4
  Bottom Layer w0.5: J17.6@20.38,51.6 20.38,51.89 20.659,52.168 R102.2@20.659,56.854
SPI_PTE(DAC): J15.16
UART_RX: J15.9 R92.1 | length 25.1
  Top Layer w0.5: v1(12.3,53) 13.426,53 13.991,52.434 13.991,51.936 13.995,51.933 13.995,50.705 v1(16.6,48.1)
  Bottom Layer w0.5: J15.9@6.34,62.83 6.499,62.671 6.499,61.818 6.792,61.525 9.399,61.525 10.407,60.516 10.407,55.593 12.3,53.7 v1(12.3,53) ; R92.1@15.633,44.8 15.633,44.825 15.858,45.05 16.307,45.05 16.6,45.343 v1(16.6,48.1)
UART_RX_ISO: J14.3 R93.2 | length 4.8
  Bottom Layer w0.5: J14.3@2.4,42.32 4.051,42.32 5.181,43.45 R93.2@6.734,43.45
UART_TX: J15.10 R94.1 | length 26.4
  Top Layer w0.5: v1(14.556,53.251) 15.977,53.251 16.55,52.678 16.55,49.656 17.3,48.906 v1(17.3,47.6)
  Bottom Layer w0.5: J15.10@8.88,62.83 9.083,62.83 11.107,60.806 11.107,56.209 14.065,53.251 v1(14.556,53.251) ; R94.1@15.883,41.75 17.3,43.167 v1(17.3,47.6)
UART_TX_ISO: J14.2 R95.2 | length 4.8
  Bottom Layer w0.5: J14.2@2.4,39.78 4.615,39.78 5.448,38.947 6.54,38.947 R95.2@6.738,38.75
Ubus: C38.1 C42.2 C59.1 D5.1 R47.2 TPDCBUS.1 U4.5 U4.8 U7.27 | length 21.1
  Bottom Layer w0.5: C42.2@33.8,28.95 33.972,29.122 34.937,29.122 35.397,29.582 35.399,29.582 38.65,32.833 38.65,34.9 41.265,37.515 42.895,37.515 D5.1@44.38,39
  Bottom Layer w1: 49.913,44.338 49.932,44.357 R47.2@49.932,49.5
VDC_AD: C56.1 J18.10 R54.1 R57.2 | length 51.4
  Top Layer w0.5: v1(28,70.209) 28,67.458 v1(29.146,66.313) ; v2(37.1,54) 41.519,54 v2(41.524,53.996)
  Bottom Layer w0.5: v1(28,70.209) C56.1@25.952,70.209 25.952,72.267 27.61,73.925 32.754,73.925 J18.10@34.36,75.53 ; v1(29.146,66.313) 31.124,66.313 31.85,65.587 31.85,52.53 32.927,51.453 33.398,51.453 33.416,51.435 35.304,51.435 37.1,53.232 v2(37.1,54) ; v2(41.524,53.996) 41.528,54 R57.2@45,54
  Bottom Layer w1: R54.1@44.985,52.073 45,52.088 R57.2@45,54
VU_AD: C73.1 J16.4 R70.1 R74.2 | length 92.1
  Top Layer w0.2: v1(22.9,78.275) 22.91,78.265 22.91,76.61 J16.4@22.92,76.6
  Bottom Layer w0.2: v1(22.9,78.275) 43.044,78.275 45.269,80.5 53.315,80.5 55.786,78.029 74.293,78.029 76.175,76.147 76.175,76.117 76.2,76.092 76.2,73.553 77.915,71.838 77.915,61.2 76.761,60.046 76.761,54.747 75.65,53.636 R70.1@75.65,51.9
  Bottom Layer w0.5: R74.2@20.166,70.178 C73.1@21.721,70.178 21.721,72.146 22.92,73.344 J16.4@22.92,76.6
VV_AD: C70.1 J16.1 R71.1 R75.2 | length 71.7
  Bottom Layer w0.2: J16.1@30.54,76.6 33.839,76.6 33.894,76.655 39.607,76.655 39.9,76.363 39.925,76.363 40.3,75.988 R75.2@40.3,75.963 C70.1@41.933,75.963 42.631,75.963 43.244,76.577 43.244,77.344 45.6,79.7 52.806,79.7 55.277,77.229 73.932,77.229 75.4,75.761 75.4,73.076 77.1,71.376 77.1,61.552 76.676,61.128 74.678,61.128 74.398,60.848 74.398,57.878 75.65,56.626 R71.1@75.65,56.351
VW_AD: C71.1 J16.5 R72.1 R76.2 | length 85.3
  Bottom Layer w0.2: J16.5@20.38,76.6 21.505,77.725 43.059,77.725 45.434,80.1 52.972,80.1 55.347,77.725 55.525,77.725 55.621,77.629 74.097,77.629 75.8,75.926 75.8,73.295 77.5,71.595 77.5,61.369 76.791,60.66 76.2,60.66 75.65,60.11 R72.1@75.65,59.835
  Bottom Layer w0.5: R76.2@16.923,70.178 C71.1@18.559,70.178 18.559,71.812 20.38,73.633 J16.5@20.38,76.6
pads on no net: D5. J15.8 J15.11 J15.12 J17.3 LBL1.0 M46.1 M46.2 M47.1 M49.1 M49.2 M50.1 M50.2 M51.1 M51.2 M52.1 M52.2 M53.1 M54.1 M55.1 M57.2 M58.2 MP1. MP2. MP3. MP4. RT1.1S RT1.2S U4.6 U6.4 U7. U7.12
